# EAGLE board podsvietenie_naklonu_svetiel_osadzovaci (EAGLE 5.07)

No outline drawn. Coordinates in mm, seen from the top.
Copper layers (1*16): Top 0.035mm / dielectric 1.5mm / Bottom 0.035mm
Design rules "default *": minimum track width 10mil, minimum drill 24mil, track to track 8mil, track to pad 8mil, pad to pad 8mil, via to via 8mil, smd to smd 8mil, copper to edge 40mil, drill to drill 8mil, minimum pad ring 12mil, minimum via ring 8mil, stop-mask expansion 4mil, vias tented up to drill 0mil, thermal gap 10mil

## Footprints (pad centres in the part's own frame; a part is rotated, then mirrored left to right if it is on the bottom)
1206 = smd 1.6 x 1.803: A -1.422,0; C 1.422,0

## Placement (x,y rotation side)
LED1  [1206]  3,4.5 0 top
LED2  [1206]  8,4.5 0 top
LED3  [1206]  13,4.5 0 top
LED4  [1206]  18,4.5 0 top
LED5  [1206]  23,4.5 0 top
LED6  [1206]  29,4.5 0 top

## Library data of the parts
LED1-LED6 = led

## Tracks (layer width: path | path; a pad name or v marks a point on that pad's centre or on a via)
(copper drawn outside any net)
  shapes: Top area x7

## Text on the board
Top: +12V | 0V | by FoXo
Doplnky: Podsvietenie náklonu svetlometov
